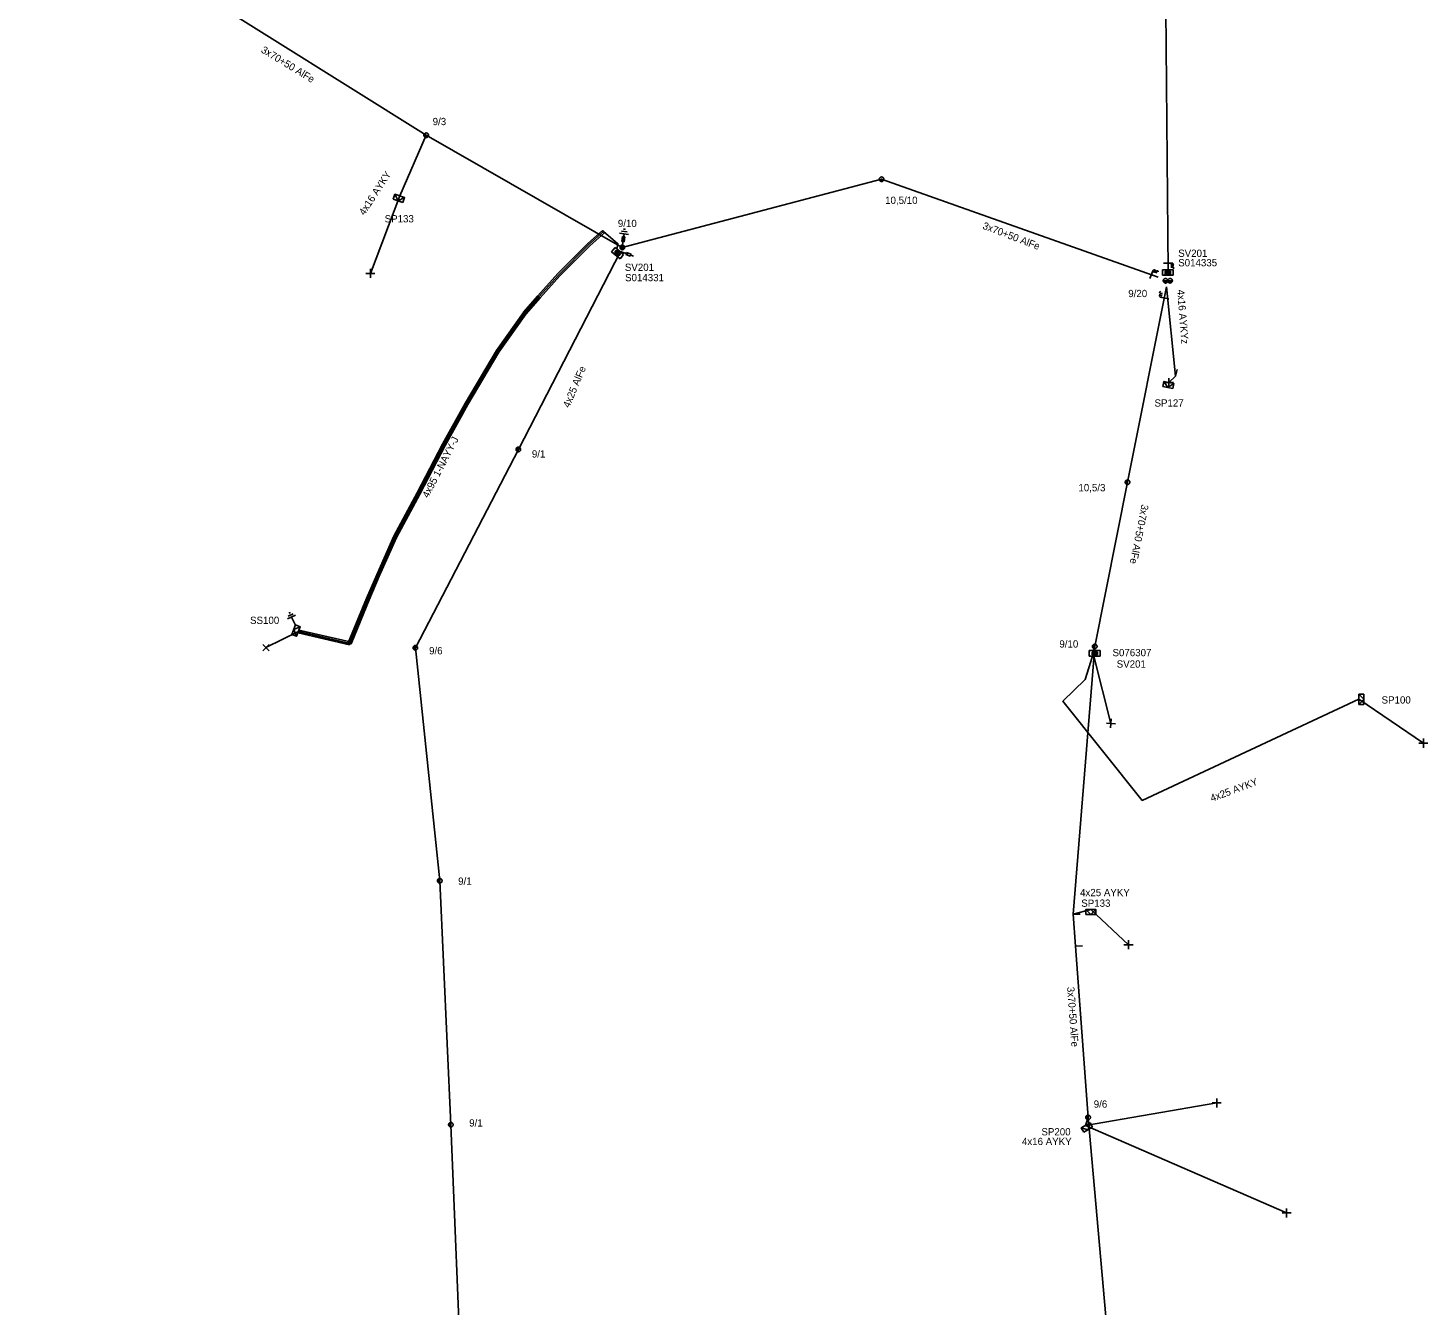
# Model space of a CAD drawing. Extents: x -717562 to -713845, y -1151196 to -1143903.
# Drawn here: x -714325.5 to -714132.9, y -1146496.9 to -1146321.1 of the extents above; entities that cross this region are included whole.
import ezdxf

# ---------------------------------------------------------------- set-up
doc = ezdxf.new("R2010")
doc.units = 0
for name, color, linetype in [('Vrstva 1', 7, 'Continuous'), ('Vrstva 12', 7, 'Continuous'), ('Vrstva 13', 7, 'Continuous'), ('Vrstva 14', 7, 'Continuous'), ('Vrstva 15', 7, 'Continuous'), ('Vrstva 16', 7, 'Continuous'), ('Vrstva 18', 7, 'Continuous'), ('Vrstva 2', 7, 'Continuous'), ('Vrstva 20', 7, 'Continuous'), ('Vrstva 28', 7, 'Continuous'), ('Vrstva 29', 7, 'Continuous'), ('Vrstva 30', 7, 'Continuous'), ('Vrstva 31', 7, 'Continuous'), ('Vrstva 33', 7, 'Continuous'), ('Vrstva 34', 7, 'Continuous'), ('Vrstva 5', 7, 'Continuous'), ('Vrstva 52', 7, 'Continuous'), ('Vrstva 54', 7, 'Continuous'), ('Vrstva 55', 7, 'Continuous'), ('Vrstva 59', 7, 'Continuous'), ('Vrstva 6', 7, 'Continuous'), ('Vrstva 8', 7, 'Continuous'), ('Vrstva 9', 7, 'Continuous')]:
    doc.layers.add(name, color=color, linetype=linetype)

# ---------------------------------------------------------------- blocks, each defined once
blk = doc.blocks.new('NN440')
at = {"layer": 'Vrstva 2'}
for points in [[(0.63, 0), (0.63, 0.06), (0.62, 0.13), (0.6, 0.19), (0.58, 0.25), (0.55, 0.31), (0.51, 0.37), (0.47, 0.42), (0.42, 0.46), (0.37, 0.51), (0.32, 0.54), (0.26, 0.57), (0.2, 0.59), (0.13, 0.61), (0.07, 0.62), (0, 0.63), (-0.06, 0.62), (-0.13, 0.61), (-0.19, 0.59), (-0.26, 0.57), (-0.31, 0.54), (-0.37, 0.51), (-0.42, 0.46), (-0.47, 0.42), (-0.51, 0.37), (-0.54, 0.31), (-0.57, 0.25), (-0.6, 0.19), (-0.62, 0.13), (-0.63, 0.06), (-0.63, 0), (-0.63, -0.07), (-0.62, -0.14), (-0.6, -0.2), (-0.57, -0.26), (-0.54, -0.32), (-0.51, -0.37), (-0.47, -0.43), (-0.42, -0.47), (-0.37, -0.51), (-0.31, -0.55), (-0.26, -0.58), (-0.19, -0.6), (-0.13, -0.62), (-0.06, -0.63), (0, -0.63), (0.07, -0.63), (0.13, -0.62), (0.2, -0.6), (0.26, -0.58), (0.32, -0.55), (0.37, -0.51), (0.42, -0.47), (0.47, -0.43), (0.51, -0.37), (0.55, -0.32), (0.58, -0.26), (0.6, -0.2), (0.62, -0.14), (0.63, -0.07), (0.63, 0)], [(-0.63, 0), (0.63, 0)], [(-0.6, -0.18), (0.57, -0.18)], [(-0.51, -0.32), (0.5, -0.32)], [(-0.37, -0.47), (0.35, -0.47)]]:
    blk.add_lwpolyline(points, dxfattribs=at)
blk = doc.blocks.new('NN450')
at = {"layer": 'Vrstva 2'}
for points in [[(0, 0), (0, 0.07), (-0.01, 0.13), (-0.03, 0.19), (-0.05, 0.25), (-0.08, 0.31), (-0.12, 0.37), (-0.16, 0.42), (-0.21, 0.46), (-0.26, 0.51), (-0.31, 0.54), (-0.37, 0.57), (-0.43, 0.59), (-0.5, 0.61), (-0.56, 0.62), (-0.63, 0.62), (-0.69, 0.62), (-0.75, 0.61), (-0.82, 0.59), (-0.88, 0.57), (-0.94, 0.54), (-0.99, 0.51), (-1.04, 0.46), (-1.09, 0.42), (-1.13, 0.37), (-1.17, 0.31), (-1.2, 0.25), (-1.22, 0.19), (-1.24, 0.13), (-1.25, 0.07), (-1.25, 0), (-1.25, -0.07), (-1.24, -0.13), (-1.22, -0.19), (-1.2, -0.25), (-1.17, -0.31), (-1.13, -0.37), (-1.09, -0.42), (-1.04, -0.46), (-0.99, -0.51), (-0.94, -0.54), (-0.88, -0.57), (-0.82, -0.59), (-0.75, -0.61), (-0.69, -0.62), (-0.62, -0.63), (-0.56, -0.62), (-0.5, -0.61), (-0.43, -0.59), (-0.37, -0.57), (-0.31, -0.54), (-0.26, -0.51), (-0.21, -0.46), (-0.16, -0.42), (-0.12, -0.37), (-0.08, -0.31), (-0.05, -0.25), (-0.03, -0.19), (-0.01, -0.13), (0, -0.07), (0, 0)], [(1.25, 0), (1.25, 0.07), (1.24, 0.13), (1.22, 0.19), (1.2, 0.25), (1.17, 0.31), (1.13, 0.37), (1.09, 0.42), (1.04, 0.46), (0.99, 0.51), (0.94, 0.54), (0.88, 0.57), (0.82, 0.59), (0.75, 0.61), (0.69, 0.62), (0.62, 0.62), (0.56, 0.62), (0.5, 0.61), (0.43, 0.59), (0.37, 0.57), (0.31, 0.54), (0.26, 0.51), (0.21, 0.46), (0.16, 0.42), (0.12, 0.37), (0.08, 0.31), (0.05, 0.25), (0.03, 0.19), (0.01, 0.13), (0, 0.07), (0, 0), (0, -0.07), (0.01, -0.13), (0.03, -0.19), (0.05, -0.25), (0.08, -0.31), (0.12, -0.37), (0.16, -0.42), (0.21, -0.46), (0.26, -0.51), (0.31, -0.54), (0.37, -0.57), (0.43, -0.59), (0.5, -0.61), (0.56, -0.62), (0.63, -0.63), (0.69, -0.62), (0.75, -0.61), (0.82, -0.59), (0.88, -0.57), (0.94, -0.54), (0.99, -0.51), (1.04, -0.46), (1.09, -0.42), (1.13, -0.37), (1.17, -0.31), (1.2, -0.25), (1.22, -0.19), (1.24, -0.13), (1.25, -0.07), (1.25, 0)], [(-1.25, 0), (1.25, 0)], [(-1.23, -0.16), (-0.02, -0.16)], [(-1.16, -0.32), (-0.09, -0.32)], [(-1.03, -0.47), (-0.22, -0.47)], [(0.02, -0.16), (1.23, -0.16)], [(0.09, -0.32), (1.16, -0.32)], [(0.22, -0.47), (1.03, -0.47)]]:
    blk.add_lwpolyline(points, dxfattribs=at)
blk = doc.blocks.new('NN840')
at = {"layer": 'Vrstva 15'}
for points in [[(0, 0.62), (0, -0.63)], [(-0.75, -0.71), (-0.75, -0.66)], [(-0.73, -0.76), (-0.75, -0.71)], [(-0.66, -0.8), (-0.73, -0.76)], [(-0.63, -0.8), (-0.66, -0.8)], [(-0.56, -0.76), (-0.63, -0.8)], [(-0.54, -0.71), (-0.56, -0.76)], [(-0.54, -0.38), (-0.54, -0.71)], [(-0.33, -0.38), (-0.33, -0.8)], [(-0.33, -0.64), (-0.13, -0.38)], [(-0.26, -0.56), (-0.09, -0.8)]]:
    blk.add_lwpolyline(points, dxfattribs=at)
blk = doc.blocks.new('NN800')
at = {"layer": 'Vrstva 1'}
for points in [[(-0.44, 0.44), (0.44, -0.44)], [(-0.44, -0.44), (0.44, 0.44)]]:
    blk.add_lwpolyline(points, dxfattribs=at)
blk = doc.blocks.new('NN820')
at = {"layer": 'Vrstva 13'}
for points in [[(0, 0), (0, -1.05)], [(-0.16, -0.81), (0.16, -0.81)], [(-0.16, -1.47), (-0.16, -0.81)], [(0.16, -1.47), (-0.16, -1.47)], [(0, -1.05), (-0.06, -0.93)], [(0, -1.05), (0.06, -0.93)], [(0, -1.47), (0, -1.87)], [(0.16, -0.81), (0.16, -1.47)]]:
    blk.add_lwpolyline(points, dxfattribs=at)
blk = doc.blocks.new('NN620')
at = {"layer": 'Vrstva 8'}
for points in [[(0.75, 0), (-0.75, 0)], [(-0.75, 0), (-0.75, -0.75)], [(0.75, -0.75), (0.75, 0)], [(-0.75, -0.75), (0.75, -0.75)], [(0.37, -0.18), (-0.38, -0.18)], [(-0.38, -0.18), (-0.38, -0.56)], [(-0.38, -0.56), (0.37, -0.56)], [(0.32, -0.23), (-0.33, -0.23)], [(-0.33, -0.23), (-0.33, -0.51)], [(-0.33, -0.51), (0.32, -0.51)], [(0.27, -0.27), (-0.28, -0.27)], [(-0.28, -0.27), (-0.28, -0.46)], [(-0.28, -0.46), (0.27, -0.46)], [(0.23, -0.32), (-0.23, -0.32)], [(-0.23, -0.32), (-0.23, -0.42)], [(-0.23, -0.42), (0.23, -0.42)], [(-0.19, -0.37), (0.19, -0.37)], [(0.23, -0.42), (0.23, -0.32)], [(0.27, -0.46), (0.27, -0.27)], [(0.32, -0.51), (0.32, -0.23)], [(0.37, -0.56), (0.37, -0.18)]]:
    blk.add_lwpolyline(points, dxfattribs=at)
blk = doc.blocks.new('NN630')
at = {"layer": 'Vrstva 9'}
for points in [[(0, -0.7), (-0.7, 0)], [(-0.7, -0.7), (-0.7, 0), (0.7, 0), (0.7, -0.7)], [(-0.7, -0.7), (0.7, -0.7)], [(0, -0.7), (0.7, 0)]]:
    blk.add_lwpolyline(points, dxfattribs=at)
blk = doc.blocks.new('NN810')
at = {"layer": 'Vrstva 14'}
for points in [[(0.63, -1.89), (-0.62, -1.89)], [(0, -0.64), (0, -1.89)], [(0.39, -2.2), (-0.4, -2.2)], [(0, -2.52), (-0.12, -2.52)], [(0.14, -2.52), (0, -2.52)]]:
    blk.add_lwpolyline(points, dxfattribs=at)
blk = doc.blocks.new('NN510')
at = {"layer": 'Vrstva 2'}
blk.add_lwpolyline([(0, 0), (0, 0.94)], dxfattribs=at)

msp = doc.modelspace()

# ---------------------------------------------------------------- linework, layer by layer
at = {"layer": 'Vrstva 1'}
for points in [[(-714186.1, -1146265.59), (-714172.57, -1146301.12), (-714170.46, -1146310.45), (-714168.98, -1146318.59), (-714168.7, -1146354.5)], [(-714325.54, -1146304.96), (-714302.73, -1146315.83), (-714270.76, -1146335.87), (-714243.78, -1146351.3)], [(-714243.78, -1146351.3), (-714208.11, -1146341.91), (-714170.07, -1146355.38)], [(-714244.01, -1146351.87), (-714258.08, -1146379.09), (-714272.25, -1146406.38), (-714268.89, -1146438.43), (-714267.37, -1146471.99), (-714265.86, -1146508.97), (-714252.61, -1146533.5), (-714234.76, -1146566.52), (-714216.05, -1146608.02), (-714194.42, -1146636.29), (-714172.31, -1146659.2)], [(-714168.9, -1146356.73), (-714174.27, -1146383.6), (-714178.78, -1146406.19)], [(-714178.78, -1146406.19), (-714181.73, -1146443.01), (-714181.42, -1146447.42), (-714179.69, -1146470.98), (-714176.38, -1146508.17)]]:
    msp.add_lwpolyline(points, dxfattribs=at)
at = {"layer": 'Vrstva 20'}
for points in [[(-714246.25, -1146349.28), (-714248.22, -1146351.05), (-714252.37, -1146355.19), (-714255.1, -1146358.22), (-714257.05, -1146360.49), (-714257.35, -1146360.23), (-714255.4, -1146357.96), (-714252.67, -1146354.91), (-714248.5, -1146350.75), (-714246.51, -1146348.98)], [(-714257.04, -1146360.48), (-714260.76, -1146365.69), (-714265.03, -1146372.89), (-714268.16, -1146378.53), (-714271.63, -1146385.25), (-714274.83, -1146391.2), (-714277.21, -1146396.52), (-714278.6, -1146399.76), (-714281.09, -1146405.85), (-714281.47, -1146405.69), (-714278.96, -1146399.6), (-714277.57, -1146396.36), (-714275.19, -1146391.02), (-714271.99, -1146385.07), (-714268.52, -1146378.35), (-714265.37, -1146372.69), (-714261.1, -1146365.47), (-714257.36, -1146360.24)], [(-714288.28, -1146403.94), (-714281.23, -1146405.58), (-714281.33, -1146405.96), (-714288.38, -1146404.32)]]:
    msp.add_lwpolyline(points, close=True, dxfattribs=at)
at = {"layer": 'Vrstva 5'}
for points in [[(-714244.51, -1146351.55), (-714244.39, -1146350.79), (-714246.38, -1146349.13), (-714248.36, -1146350.9), (-714252.52, -1146355.05), (-714255.25, -1146358.09), (-714257.2, -1146360.36), (-714260.93, -1146365.58), (-714265.2, -1146372.79), (-714268.34, -1146378.44), (-714271.81, -1146385.16), (-714275.01, -1146391.11), (-714277.39, -1146396.44), (-714278.78, -1146399.68), (-714281.28, -1146405.77), (-714288.33, -1146404.13)], [(-714178.78, -1146406.19), (-714179, -1146406.82)]]:
    msp.add_lwpolyline(points, dxfattribs=at)
at = {"layer": 'Vrstva 52'}
for points in [[(-714270.76, -1146335.87), (-714274.4, -1146344.22)], [(-714179.11, -1146407.52), (-714180.11, -1146410.76), (-714183.17, -1146413.71), (-714172.24, -1146427.37), (-714142.44, -1146413.46)], [(-714181.73, -1146443.01), (-714179.32, -1146442.39)], [(-714179.69, -1146470.98), (-714180.04, -1146472.08)]]:
    msp.add_lwpolyline(points, dxfattribs=at)
at = {"layer": 'Vrstva 54'}
msp.add_lwpolyline([(-714168.9, -1146356.73), (-714167.68, -1146369.02), (-714168.58, -1146369.89)], dxfattribs=at)
at = {"layer": 'Vrstva 59'}
for points in [[(-714274.4, -1146344.22), (-714278.44, -1146354.88)], [(-714288.33, -1146404.13), (-714292.8, -1146406.35)], [(-714178.91, -1146407.52), (-714176.56, -1146416.8)], [(-714142.44, -1146413.46), (-714133.56, -1146419.5)], [(-714179.32, -1146442.39), (-714174.14, -1146447.23)], [(-714180.04, -1146472.08), (-714162, -1146469)], [(-714180.04, -1146472.08), (-714152.38, -1146484.13)]]:
    msp.add_lwpolyline(points, dxfattribs=at)

# ---------------------------------------------------------------- block references
at = {"layer": 'Vrstva 13'}
for p, xscale, yscale, rotation in [((-714270.76, -1146335.87), 0.5, 0.5, -31.383019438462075), ((-714208.11, -1146341.92), 0.5, 0.5000000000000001, 4.899997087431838), ((-714243.78, -1146351.3), 0.5, 0.5, -31.383019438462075), ((-714258.08, -1146379.09), 0.5, 0.49999999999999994, -116.46857226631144), ((-714174.27, -1146383.6), 0.5, 0.49999999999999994, -101.2924083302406), ((-714272.25, -1146406.38), 0.5, 0.5000000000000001, -116.46857220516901), ((-714178.78, -1146406.19), 0.5, 0.5, -90), ((-714268.89, -1146438.43), 0.5000000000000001, 0.4999999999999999, -87.40667499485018), ((-714179.69, -1146470.98), 0.5000000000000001, 0.5, -85.80735326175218), ((-714267.37, -1146471.99), 0.5, 0.5, -87.4066750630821)]:
    msp.add_blockref('NN440', p, dxfattribs=dict(at, xscale=xscale, yscale=yscale, rotation=rotation))
at = {"layer": 'Vrstva 13', "xscale": 0.5, "yscale": 0.5}
msp.add_blockref('NN450', (-714168.73, -1146355.89), dxfattribs=at)
at = {"layer": 'Vrstva 13'}
for p, rotation in [((-714167.69, -1146369.02), -14.754252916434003), ((-714181.73, -1146443.01), -90), ((-714181.42, -1146447.41), -88.0284250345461)]:
    msp.add_blockref('NN510', p, dxfattribs=dict(at, rotation=rotation))
at = {"layer": 'Vrstva 15'}
for p, rotation in [((-714243.78, -1146351.3), 172.67477401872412), ((-714288.46, -1146403.85), -154.44858778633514)]:
    msp.add_blockref('NN810', p, dxfattribs=dict(at, rotation=rotation))
at = {"layer": 'Vrstva 16'}
for p, rotation in [((-714243.78, -1146351.3), 172.67477401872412), ((-714244.01, -1146351.87), 70.61686262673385)]:
    msp.add_blockref('NN820', p, dxfattribs=dict(at, rotation=rotation))
at = {"layer": 'Vrstva 18'}
for p, rotation in [((-714170.99, -1146355.02), 158.96439441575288), ((-714168.69, -1146353.47), 88.9898249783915), ((-714169.21, -1146358.26), -101.29240829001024)]:
    msp.add_blockref('NN840', p, dxfattribs=dict(at, rotation=rotation))
at = {"layer": 'Vrstva 28'}
for p, rotation in [((-714244.19, -1146351.8), -39.848894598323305), ((-714168.73, -1146355.14), 180), ((-714178.78, -1146407.52), 180)]:
    msp.add_blockref('NN620', p, dxfattribs=dict(at, rotation=rotation))
at = {"layer": 'Vrstva 31'}
for p, rotation in [((-714274.4, -1146344.22), -19.665455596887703), ((-714168.58, -1146369.89), -12.513677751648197), ((-714288.33, -1146404.13), -110.75349948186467), ((-714142.44, -1146413.46), 90), ((-714180.04, -1146472.08), 29.631536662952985)]:
    msp.add_blockref('NN630', p, dxfattribs=dict(at, rotation=rotation))
msp.add_blockref('NN630', (-714179.32, -1146442.39), dxfattribs=at)
at = {"layer": 'Vrstva 34'}
for p, rotation in [((-714278.44, -1146354.88), 44.99999995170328), ((-714168.58, -1146369.89), 45), ((-714176.56, -1146416.79), 131.71510556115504), ((-714133.56, -1146419.5), 45), ((-714174.14, -1146447.23), 45), ((-714162, -1146469), 45), ((-714152.38, -1146484.13), 45)]:
    msp.add_blockref('NN800', p, dxfattribs=dict(at, rotation=rotation))
msp.add_blockref('NN800', (-714292.8, -1146406.35), dxfattribs=at)

# ---------------------------------------------------------------- texts
at = {"layer": 'Vrstva 12'}
for s, p in [('9/3', (-714269.87, -1146334.48)), ('10,5/10', (-714207.62, -1146345.32)), ('9/10', (-714244.39, -1146348.5)), ('9/20', (-714174.17, -1146358.14)), ('9/1', (-714256.22, -1146380.21)), ('10,5/3', (-714181.03, -1146384.85)), ('9/10', (-714183.65, -1146406.35)), ('9/6', (-714270.36, -1146407.28)), ('9/1', (-714266.36, -1146438.98)), ('9/6', (-714178.92, -1146469.65)), ('9/1', (-714264.84, -1146472.24))]:
    msp.add_text(s, height=1, dxfattribs=at).set_placement(p)
at = {"layer": 'Vrstva 2'}
for s, rotation, p in [('3x70+50 AlFe', 328.617, (-714293.57, -1146324.39)), ('3x70+50 AlFe', 338.952, (-714194.29, -1146348.7)), ('4x25 AlFe', 67.302, (-714251.07, -1146373.44)), ('3x70+50 AlFe', 258.709, (-714172.34, -1146386.6)), ('3x70+50 AlFe', 274.193, (-714182.59, -1146453.05))]:
    msp.add_text(s, height=1, rotation=rotation, dxfattribs=at).set_placement(p)
at = {"layer": 'Vrstva 29'}
for s, p in [('S014335', (-714167.3, -1146353.9)), ('S014331', (-714243.4, -1146355.95)), ('S076307', (-714176.34, -1146407.54))]:
    msp.add_text(s, height=1, dxfattribs=at).set_placement(p)
at = {"layer": 'Vrstva 30'}
for p in [(-714167.3, -1146352.6), (-714243.43, -1146354.53), (-714175.76, -1146409.11)]:
    msp.add_text('SV201', height=1, dxfattribs=at).set_placement(p)
at = {"layer": 'Vrstva 33'}
for s, p in [('SP133', (-714276.47, -1146347.86)), ('SP127', (-714170.56, -1146373.2)), ('SS100', (-714294.99, -1146403.1)), ('SP100', (-714139.32, -1146414.05)), ('SP133', (-714180.64, -1146442.01)), ('SP200', (-714186.12, -1146473.46))]:
    msp.add_text(s, height=1, dxfattribs=at).set_placement(p)
at = {"layer": 'Vrstva 54'}
for s, rotation, p in [('4x16 AYKY', 56.928, (-714279.26, -1146346.97)), ('4x25 AYKY', 20.371, (-714162.67, -1146427.58))]:
    msp.add_text(s, height=1, rotation=rotation, dxfattribs=at).set_placement(p)
for s, p in [('4x25 AYKY', (-714180.8, -1146440.55)), ('4x16 AYKY', (-714188.8, -1146474.79))]:
    msp.add_text(s, height=1, dxfattribs=at).set_placement(p)
at = {"layer": 'Vrstva 55'}
msp.add_text('4x16 AYKYz', height=1, rotation=274.573, dxfattribs=at).set_placement((-714167.45, -1146357.14))
at = {"layer": 'Vrstva 6'}
msp.add_text('4x95 1-NAYY-J', height=1, rotation=62.69, dxfattribs=at).set_placement((-714270.48, -1146385.85))

doc.saveas('drawing.dxf')
